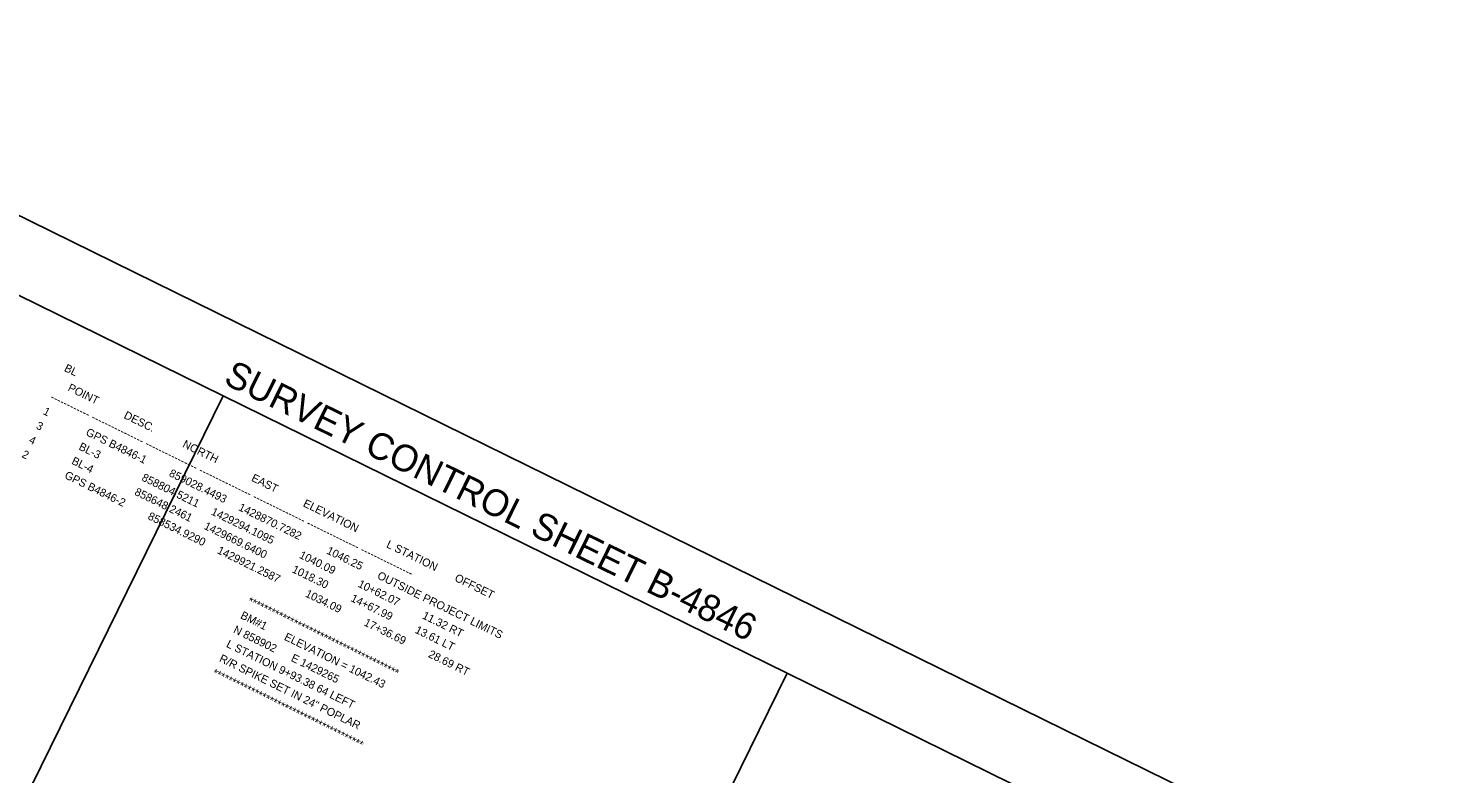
# Model space of a CAD drawing. Extents: x 1428428 to 1430511, y 857911 to 859585.
# Drawn here: x 1429385 to 1430484, y 859002 to 859585 of the extents above; entities that cross this region are included whole.
import ezdxf

# ---------------------------------------------------------------- set-up
doc = ezdxf.new("R2010")
doc.units = 0
for name, color, linetype in [('CTL Sheet Border CELL', 7, 'Continuous'), ('CTL Sheet Text', 7, 'Continuous'), ('Scratch_Level_3', 7, 'Continuous')]:
    doc.layers.add(name, color=color, linetype=linetype)

msp = doc.modelspace()

# ---------------------------------------------------------------- linework, layer by layer
at = {"layer": 'CTL Sheet Border CELL'}
msp.add_lwpolyline([(1430484, 858893.6), (1429079.6, 859584.7), (1428595.9, 858601.6), (1430000.3, 857910.6)], close=True, dxfattribs=at)
at = {"layer": 'Scratch_Level_3'}
for p, q in [((1429096.5, 859514), (1429537, 859297.3)), ((1429537, 859297.3), (1429180, 858572)), ((1429537, 859297.3), (1429977.4, 859080.6)), ((1429977.4, 859080.6), (1429620.4, 858355.3)), ((1429977.4, 859080.6), (1430417.8, 858863.9))]:
    msp.add_line(p, q, dxfattribs=at)

# ---------------------------------------------------------------- texts
at = {"layer": 'CTL Sheet Border CELL'}
msp.add_text('SURVEY CONTROL SHEET B-4846', height=20.87, rotation=333.8001, dxfattribs=at).set_placement((1429536.3, 859307.2))
at = {"layer": 'CTL Sheet Text'}
for s, p in [('BL', (1429412.2, 859317)), ('    POINT          DESC.           NORTH             EAST          ELEVATION           L STATION       OFFSET', (1429406.7, 859305.8)), ('------------ ---------------- ---------------- ---------------- ---------------- ---------------- ----------------', (1429401.2, 859294.5)), ('1              GPS B4846-1         859028.4493     1428870.7282          1046.25      OUTSIDE PROJECT LIMITS                 ', (1429395.7, 859283.3)), ('3              BL-3                858804.5211     1429294.1095          1040.09         10+62.07         11.32 RT', (1429390.2, 859272.1)), ('4              BL-4                858648.2461     1429669.6400          1018.30         14+67.99         13.61 LT', (1429384.6, 859260.9)), ('2              GPS B4846-2         858534.9290     1429921.2587          1034.09         17+36.69         28.69 RT', (1429379.1, 859249.7)), ('****************************************', (1429555.4, 859135)), ('BM#1       ELEVATION = 1042.43', (1429549.8, 859123.8)), ('N 858902      E 1429265', (1429544.3, 859112.6)), ('L STATION 9+93.38 64 LEFT', (1429538.8, 859101.4)), ('R/R SPIKE SET IN 24" POPLAR', (1429533.3, 859090.1)), ('****************************************', (1429527.8, 859078.9))]:
    msp.add_text(s, height=6.25, rotation=333.8001, dxfattribs=at).set_placement(p)

doc.saveas('drawing.dxf')
